Omron CX-Programmer project NuevoProyecto (CX-Programmer 9.50)

# PLC NewPLC1: CP1L-E EM

## Global symbols (name address type ; comment)
D0 CHANNEL  ; 0
T0001 BOOL  ; T1
T0002 BOOL  ; T2
T0003 BOOL  ; T3
T0004 BOOL  ; T4
T0005 BOOL  ; T5
T0006 BOOL  ; T6
T0007 BOOL  ; T7
T0008 BOOL  ; T8

## Program P10_1 (cyclic task 0)
Local symbols
EV1 100.04 BOOL  ; EV1=X6·Pm'
EV2 100.05 BOOL  ; EV2=X13·Pm'
EVA 100.00 BOOL  ; EVA=(X1+X10)·Pm'
EVB 100.01 BOOL  ; EVB=(X2+X9)Pm'
EVC 100.02 BOOL  ; EVC=X3·Pm'
EVD 100.03 BOOL  ; EVD=X8·Pm'
Etapa_0 10.00 BOOL
Etapa_1 10.01 BOOL
Etapa_10 10.10 BOOL
Etapa_11 10.11 BOOL
Etapa_12 10.12 BOOL
Etapa_13 10.13 BOOL
Etapa_14 10.14 BOOL
Etapa_2 10.02 BOOL
Etapa_3 10.03 BOOL
Etapa_4 10.04 BOOL
Etapa_5 10.05 BOOL
Etapa_6 10.06 BOOL
Etapa_7 10.07 BOOL
Etapa_8 10.08 BOOL
Etapa_9 10.09 BOOL
FC1 0.04 BOOL  ; Final carrera 1 (CNA)
FC2 0.05 BOOL  ; Final carrera 2 (CNA)
FC3 0.06 BOOL  ; Final carrera 3 (CNA)
FC4 0.07 BOOL  ; Final carrera 4 (CNA)
KCD 100.06 BOOL  ; KCD=(X1+X2+X3+X4)·Pm'
KCI 100.07 BOOL  ; KCI=(X8+X9+X10+X11)·Pm'
KV1D 101.00 BOOL  ; KV1D=X5·Pm'
KV1I 101.01 BOOL  ; KV1I=X7·Pm'
KV2D 101.02 BOOL  ; KV2D=X14·Pm'
KV2I 101.03 BOOL  ; KV2I=X12·Pm'
P 0.02 BOOL  ; Pulsador de paro (CNC)
Pm 15.00 BOOL  ; Pm=P·X0'+Pm·R'
R 0.03 BOOL  ; Pulsador de rearme (CNA)
m1 0.00 BOOL  ; Pulsador de marcha mezcla 1 (CNA)
m2 0.01 BOOL  ; Pulsador de marcha mezcla 2 (CNA)

### Section Sección1_Etapa_0
; Etapa 0

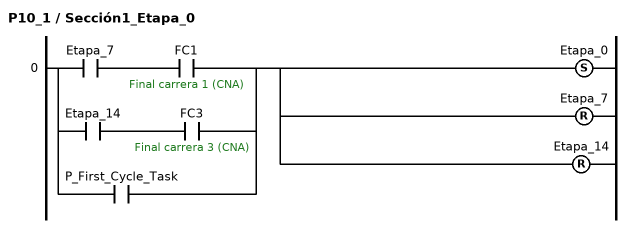
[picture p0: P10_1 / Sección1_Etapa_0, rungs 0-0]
; rung 0
LD Etapa_7
AND FC1  ; Final carrera 1 (CNA)
LD Etapa_14
AND FC3  ; Final carrera 3 (CNA)
ORLD
OR P_First_Cycle_Task
SET Etapa_0
RSET Etapa_7
RSET Etapa_14

### Section Sección2_Mezcla_1_Etapas_1_a_7
; Etapas 1 ... 7

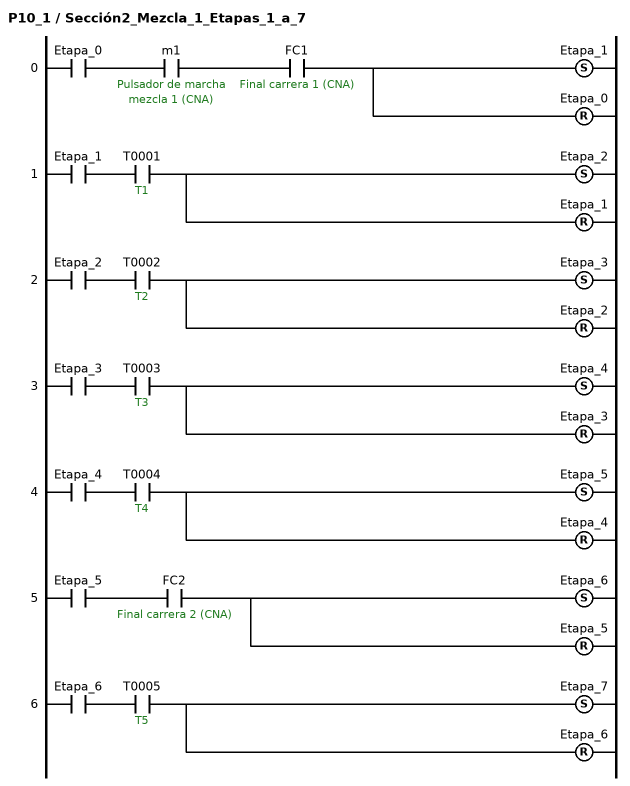
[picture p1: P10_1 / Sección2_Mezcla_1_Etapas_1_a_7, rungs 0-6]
; rung 0
LD Etapa_0
AND m1  ; Pulsador de marcha mezcla 1 (CNA)
AND FC1  ; Final carrera 1 (CNA)
SET Etapa_1
RSET Etapa_0
; rung 1
LD Etapa_1
AND T0001  ; T1
SET Etapa_2
RSET Etapa_1
; rung 2
LD Etapa_2
AND T0002  ; T2
SET Etapa_3
RSET Etapa_2
; rung 3
LD Etapa_3
AND T0003  ; T3
SET Etapa_4
RSET Etapa_3
; rung 4
LD Etapa_4
AND T0004  ; T4
SET Etapa_5
RSET Etapa_4
; rung 5
LD Etapa_5
AND FC2  ; Final carrera 2 (CNA)
SET Etapa_6
RSET Etapa_5
; rung 6
LD Etapa_6
AND T0005  ; T5
SET Etapa_7
RSET Etapa_6

### Section Sección3_Mezcla_2_Etapas_8_a_14
; Etapas 8 ... 14

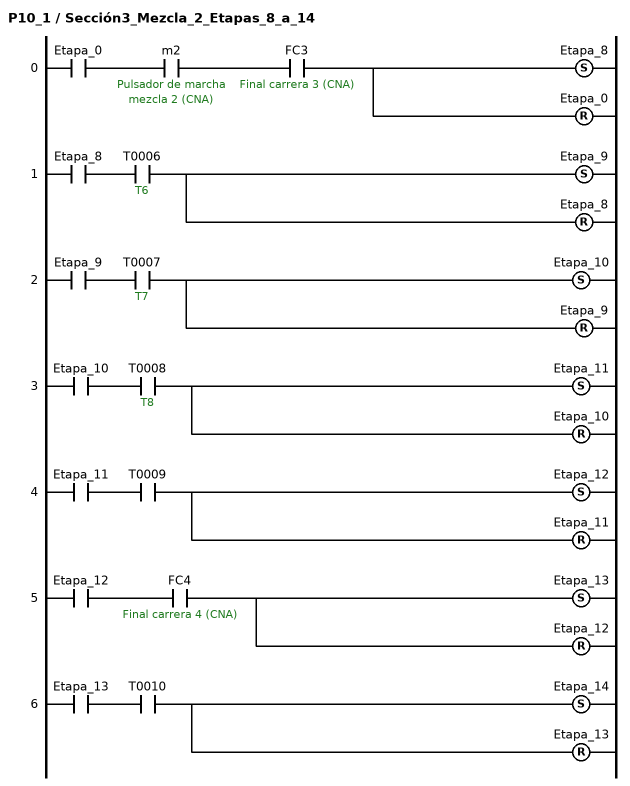
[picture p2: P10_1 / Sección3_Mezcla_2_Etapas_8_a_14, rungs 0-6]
; rung 0
LD Etapa_0
AND m2  ; Pulsador de marcha mezcla 2 (CNA)
AND FC3  ; Final carrera 3 (CNA)
SET Etapa_8
RSET Etapa_0
; rung 1
LD Etapa_8
AND T0006  ; T6
SET Etapa_9
RSET Etapa_8
; rung 2
LD Etapa_9
AND T0007  ; T7
SET Etapa_10
RSET Etapa_9
; rung 3
LD Etapa_10
AND T0008  ; T8
SET Etapa_11
RSET Etapa_10
; rung 4
LD Etapa_11
AND T0009
SET Etapa_12
RSET Etapa_11
; rung 5
LD Etapa_12
AND FC4  ; Final carrera 4 (CNA)
SET Etapa_13
RSET Etapa_12
; rung 6
LD Etapa_13
AND T0010
SET Etapa_14
RSET Etapa_13

### Section Sección4_Temporizadores
; Temporizadores

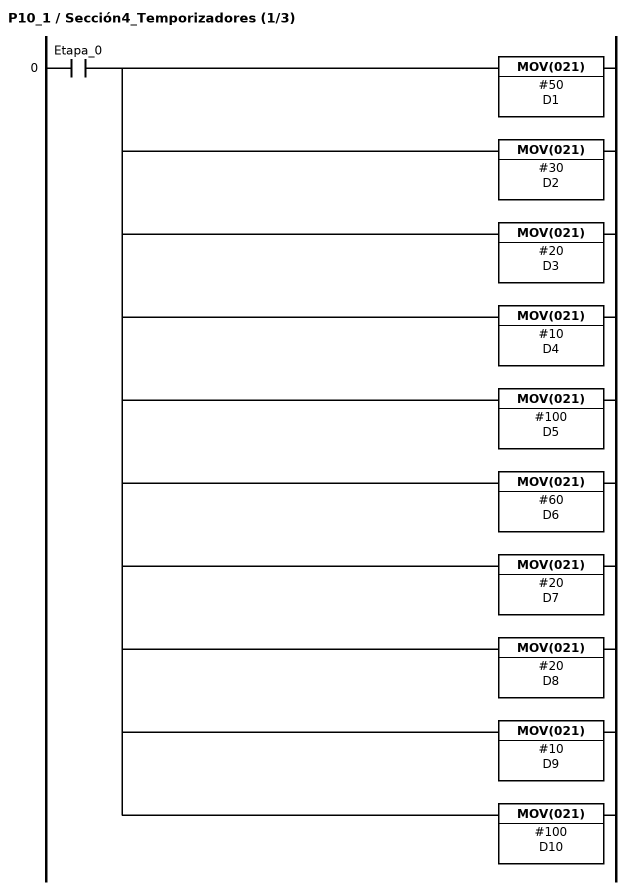
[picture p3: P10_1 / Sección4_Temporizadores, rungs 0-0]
; rung 0
LD Etapa_0
MOV(021) #50 D1
MOV(021) #30 D2
MOV(021) #20 D3
MOV(021) #10 D4
MOV(021) #100 D5
MOV(021) #60 D6
MOV(021) #20 D7
MOV(021) #20 D8
MOV(021) #10 D9
MOV(021) #100 D10

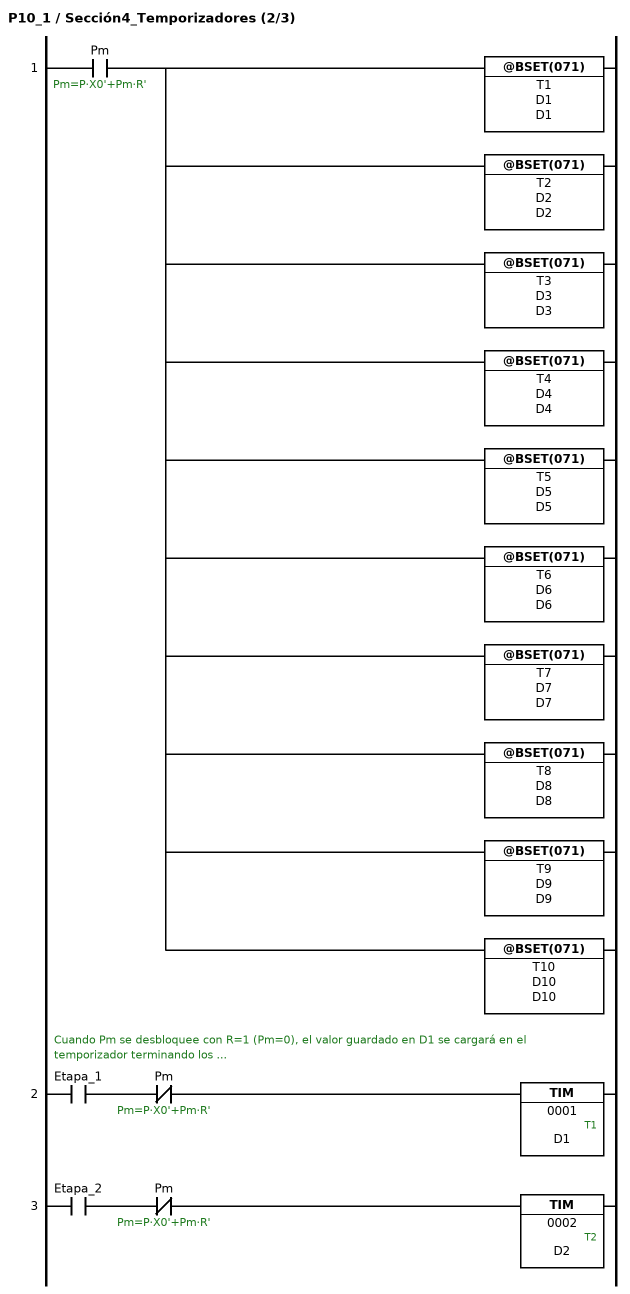
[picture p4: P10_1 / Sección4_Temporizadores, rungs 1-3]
; rung 1
LD Pm  ; Pm=P·X0'+Pm·R'
@BSET(071) T1 D1 D1  // La instrucción @BSET pasa a D1 el valor que le queda a T1 en el momento de pulsar P (Pm=P·X0'+Pm·R'=1)
@BSET(071) T2 D2 D2
@BSET(071) T3 D3 D3
@BSET(071) T4 D4 D4
@BSET(071) T5 D5 D5
@BSET(071) T6 D6 D6
@BSET(071) T7 D7 D7
@BSET(071) T8 D8 D8
@BSET(071) T9 D9 D9
@BSET(071) T10 D10 D10
; rung 2: Cuando Pm se desbloquee con R=1 (Pm=0), el valor guardado en D1 se cargará en el temporizador terminando los ...
LD Etapa_1
ANDNOT Pm  ; Pm=P·X0'+Pm·R'
TIM 0001 D1  ; T1  // ... segundos que le quedasen
; rung 3
LD Etapa_2
ANDNOT Pm  ; Pm=P·X0'+Pm·R'
TIM 0002 D2  ; T2

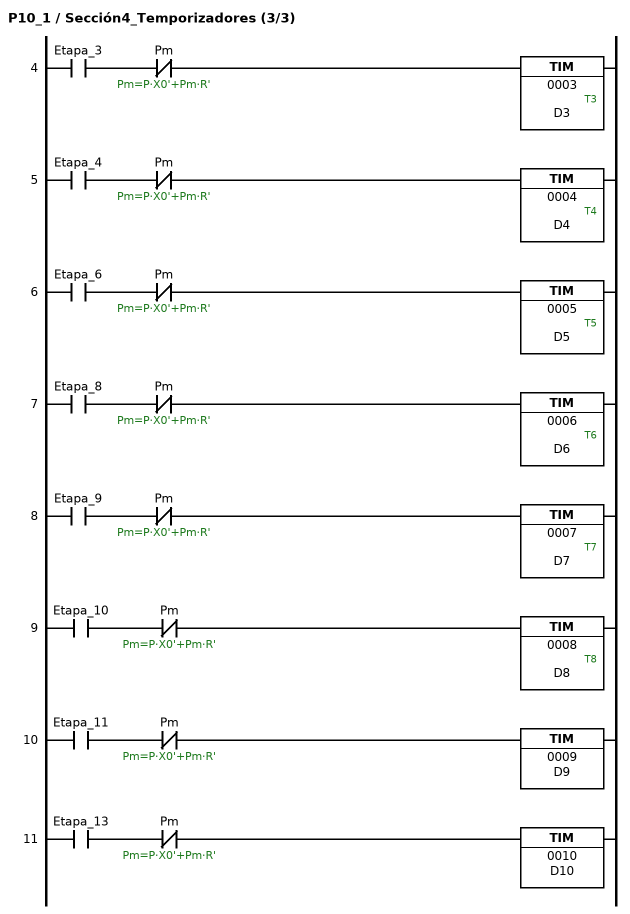
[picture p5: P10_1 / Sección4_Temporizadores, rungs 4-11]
; rung 4
LD Etapa_3
ANDNOT Pm  ; Pm=P·X0'+Pm·R'
TIM 0003 D3  ; T3
; rung 5
LD Etapa_4
ANDNOT Pm  ; Pm=P·X0'+Pm·R'
TIM 0004 D4  ; T4
; rung 6
LD Etapa_6
ANDNOT Pm  ; Pm=P·X0'+Pm·R'
TIM 0005 D5  ; T5
; rung 7
LD Etapa_8
ANDNOT Pm  ; Pm=P·X0'+Pm·R'
TIM 0006 D6  ; T6
; rung 8
LD Etapa_9
ANDNOT Pm  ; Pm=P·X0'+Pm·R'
TIM 0007 D7  ; T7
; rung 9
LD Etapa_10
ANDNOT Pm  ; Pm=P·X0'+Pm·R'
TIM 0008 D8  ; T8
; rung 10
LD Etapa_11
ANDNOT Pm  ; Pm=P·X0'+Pm·R'
TIM 0009 D9
; rung 11
LD Etapa_13
ANDNOT Pm  ; Pm=P·X0'+Pm·R'
TIM 0010 D10

### Section Sección5_Ecuación_Pm

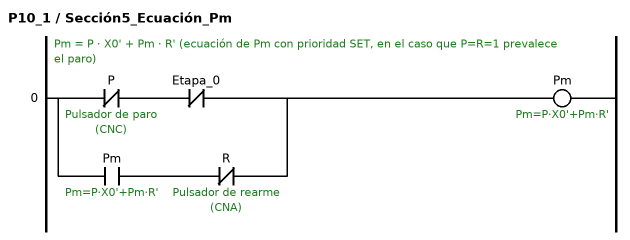
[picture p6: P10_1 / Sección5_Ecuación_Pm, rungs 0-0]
; rung 0: Pm = P · X0' + Pm · R' (ecuación de Pm con prioridad SET, en el caso que P=R=1 prevalece el paro)
LDNOT P  ; Pulsador de paro (CNC)
ANDNOT Etapa_0
LD Pm  ; Pm=P·X0'+Pm·R'
ANDNOT R  ; Pulsador de rearme (CNA)
ORLD
OUT Pm  ; Pm=P·X0'+Pm·R'

### Section Sección6_Salidas
; Salidas

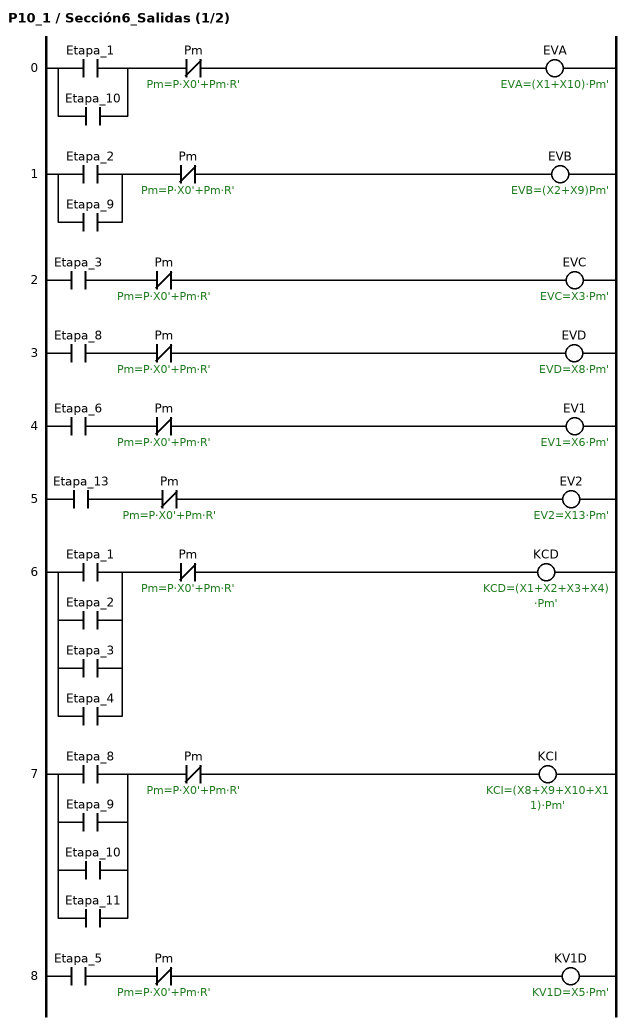
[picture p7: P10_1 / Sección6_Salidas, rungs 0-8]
; rung 0
LD Etapa_1
OR Etapa_10
ANDNOT Pm  ; Pm=P·X0'+Pm·R'
OUT EVA  ; EVA=(X1+X10)·Pm'
; rung 1
LD Etapa_2
OR Etapa_9
ANDNOT Pm  ; Pm=P·X0'+Pm·R'
OUT EVB  ; EVB=(X2+X9)Pm'
; rung 2
LD Etapa_3
ANDNOT Pm  ; Pm=P·X0'+Pm·R'
OUT EVC  ; EVC=X3·Pm'
; rung 3
LD Etapa_8
ANDNOT Pm  ; Pm=P·X0'+Pm·R'
OUT EVD  ; EVD=X8·Pm'
; rung 4
LD Etapa_6
ANDNOT Pm  ; Pm=P·X0'+Pm·R'
OUT EV1  ; EV1=X6·Pm'
; rung 5
LD Etapa_13
ANDNOT Pm  ; Pm=P·X0'+Pm·R'
OUT EV2  ; EV2=X13·Pm'
; rung 6
LD Etapa_1
OR Etapa_2
OR Etapa_3
OR Etapa_4
ANDNOT Pm  ; Pm=P·X0'+Pm·R'
OUT KCD  ; KCD=(X1+X2+X3+X4)·Pm'
; rung 7
LD Etapa_8
OR Etapa_9
OR Etapa_10
OR Etapa_11
ANDNOT Pm  ; Pm=P·X0'+Pm·R'
OUT KCI  ; KCI=(X8+X9+X10+X11)·Pm'
; rung 8
LD Etapa_5
ANDNOT Pm  ; Pm=P·X0'+Pm·R'
OUT KV1D  ; KV1D=X5·Pm'

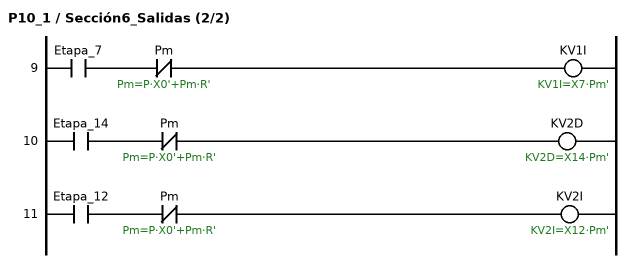
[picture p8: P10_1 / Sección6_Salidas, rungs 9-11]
; rung 9
LD Etapa_7
ANDNOT Pm  ; Pm=P·X0'+Pm·R'
OUT KV1I  ; KV1I=X7·Pm'
; rung 10
LD Etapa_14
ANDNOT Pm  ; Pm=P·X0'+Pm·R'
OUT KV2D  ; KV2D=X14·Pm'
; rung 11
LD Etapa_12
ANDNOT Pm  ; Pm=P·X0'+Pm·R'
OUT KV2I  ; KV2I=X12·Pm'

### Section Sección7_END
; END
; rung 0
END(001)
